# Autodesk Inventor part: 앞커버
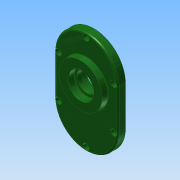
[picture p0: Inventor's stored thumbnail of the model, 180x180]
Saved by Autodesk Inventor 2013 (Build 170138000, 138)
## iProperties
Created: 2016-12
Part Number: 앞커버
Material: 알루미늄 6061
Document SubType Name: Modeling
Designer: mduedu
Density: 2.71 g/cm^3
Mass: 264.834 g
Surface Area: 264.105 cm^2
Volume: 97.7247 cm^3
Author: mduedu
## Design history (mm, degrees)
sketch "스케치1"
  geometry: L1 (40, -25)-(40, 25); L2 (-40, 25)-(-40, -25); L3 (-40, -25)-(40, 25); L4 (40, -25)-(-40, 25); A1 r 40 centre (0, 25) between (40, 25) and (-40, 25); A2 r 40 centre (0, -25) between (-40, -25) and (40, -25); 1 further point
  constraints: 8 end point, 4 point on circle, 4 tangent, 2 centre point, 2 midpoint, 1 parallel, 1 vertical
  dimensions: "d0" = 130 dimension on A2 A1; "d2" = 80 distance between parallel lines of L1 L2
extrude "돌출1" new body sketch "스케치1" distance "d3" = 10; taper "d4" = 0 deg
sketch "스케치2"
  geometry: C1 r 21 at (0, 11); 1 further point
  constraints: 1 centre point, 1 vertical alignment
  dimensions: "d5" = 42 diameter of C1; "d7" = 11 distance of C1.centre point (0, 0)
extrude "돌출2" join sketch "스케치2" distance "d8" = 7; taper "d9" = 0 deg
sketch "스케치3"
  geometry: C1 r 15 at (0, -33.1); C2 r 21 at (0, 11) reference; 1 further point
  constraints: 1 centre point, 1 vertical alignment
  dimensions: "d10" = 30 diameter of C1; "d71" = 44.1 distance of C1.centre C2.centre
extrude "돌출3" join sketch "스케치3" distance "d12" = 7; taper "d13" = 0 deg
sketch "스케치4"
  geometry: C1 r 28 at (0, 11); A1 r 21 centre (0, 11) between (8.978, -7.984) and (-8.978, -7.984) reference; 1 further point
  constraints: 1 centre point, 1 coincident
  dimensions: "d14" = 56 diameter of C1
extrude "돌출4" join sketch "스케치4" distance "d15" = 7; taper "d16" = -5 deg
hole "구멍1" diameter "d19" = 35; stored, may be unused: countersink angle "d23" = 90 deg, drill point angle "d25" = 0 deg; dims "d17" = 10, "d18" = 10, "d20" = 6, "d21" = 4, "d22" = 2, "d24" = 10
hole "구멍2" diameter "d28" = 22; stored, may be unused: countersink angle "d32" = 90 deg, drill point angle "d34" = 0 deg; dims "d26" = 10, "d27" = 10, "d29" = 6, "d30" = 4, "d31" = 2, "d33" = 7
hole "구멍3" diameter "d37" = 19; stored, may be unused: countersink angle "d41" = 90 deg, drill point angle "d43" = 0 deg; dims "d35" = 10, "d36" = 10, "d38" = 6, "d39" = 4, "d40" = 2, "d42" = 1
hole "구멍4" diameter "d46" = 32; stored, may be unused: countersink angle "d50" = 90 deg, drill point angle "d52" = 0 deg; dims "d44" = 10, "d45" = 10, "d47" = 6, "d48" = 4, "d49" = 2, "d51" = 8
hole "구멍5" diameter "d55" = 25; stored, may be unused: countersink angle "d59" = 90 deg, drill point angle "d61" = 0 deg; dims "d53" = 10, "d54" = 10, "d56" = 6, "d57" = 4, "d58" = 2, "d60" = 8
fillet "모깎기1" dims "d62" = 0.3
fillet "모깎기2" dims "d63" = 2
chamfer "모따기1" distance "d64" = 1; stored, may be unused: second distance "d65" = 2, angle "d66" = 45 deg
fillet "모깎기4" dims "d68" = 2
fillet "모깎기5" dims "d69" = 0.3
fillet "모깎기6" dims "d70" = 2
sketch "스케치5"
  geometry: L1 (-40, 25)-(-40, -25) reference; L2 (40, -25)-(40, 25) reference; L3 (35, 25)-(35, -25); L4 (-35, -25)-(-35, 25); A1 r 40 centre (0, 25) between (40, 25) and (-40, 25) reference; A2 r 40 centre (0, -25) between (-40, -25) and (40, -25) reference; A3 r 35 centre (0, 25) between (35, 25) and (-35, 25); A4 r 35 centre (0, -25) between (-35, -25) and (35, -25); 2 further points
  constraints: 5 point on circle, 4 end point, 2 centre point, 1 vertical alignment, 3 other
  dimensions: "d72" = 5 distance between parallel lines of L2 L3
sketch "스케치7"
  geometry: 1 further point
hole "구멍7" sketch "스케치7" at (0, 60) diameter "d80" = 4.5; stored, may be unused: countersink angle "d84" = 90 deg, drill point angle "d86" = 0 deg; dims "d81" = 6, "d82" = 8, "d83" = 4.6, "d85" = 8
node "솔리드1"
pattern_linear "직사각형 패턴1"
